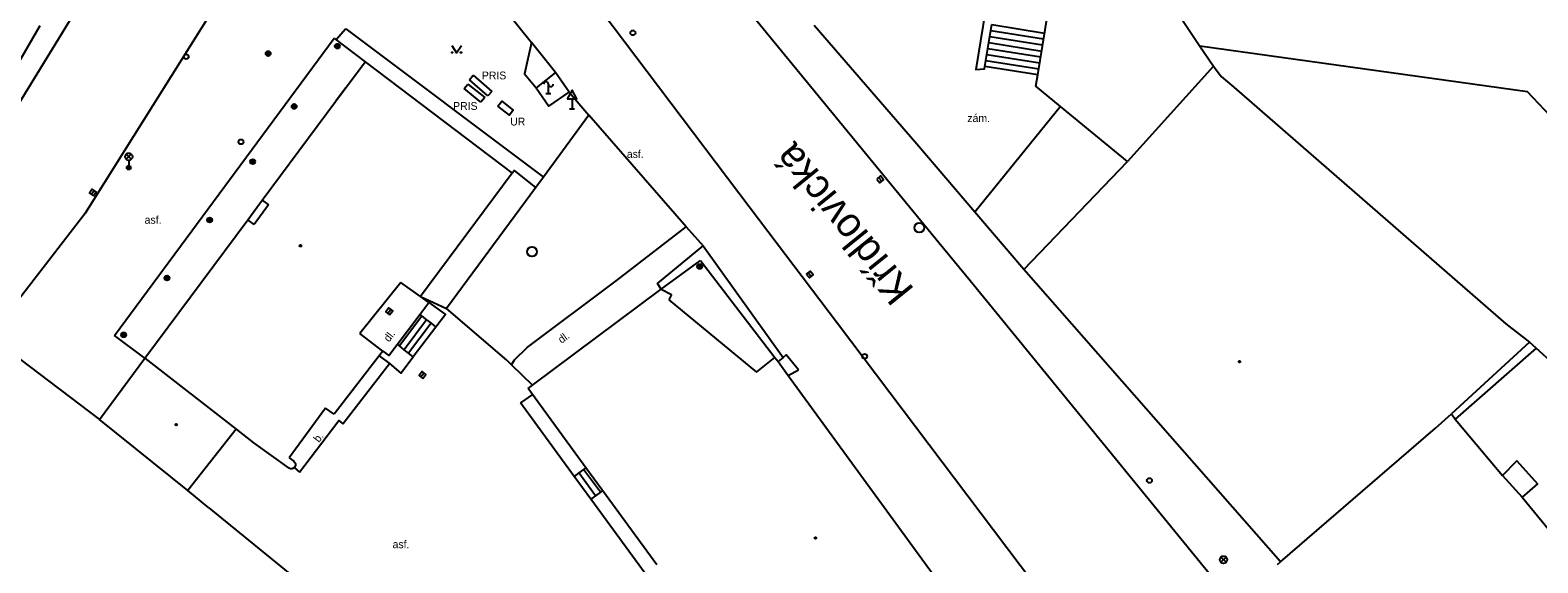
# Model space of a CAD drawing. Extents: x -599770 to -598493, y -1162076 to -1159209.
# Drawn here: x -599224.4 to -599147.3, y -1161384.7 to -1161357.5 of the extents above; entities that cross this region are included whole.
import ezdxf

# ---------------------------------------------------------------- set-up
doc = ezdxf.new("R2010")
doc.units = 0
doc.layers.add('Podklad', color=7, linetype='Continuous')

msp = doc.modelspace()

# ---------------------------------------------------------------- linework, layer by layer
at = {"layer": 'Podklad'}
for p, q in [((-599197.755, -1161360.78), (-599198.005, -1161360.78)), ((-599197.88, -1161360.78), (-599197.88, -1161360.28)), ((-599196.795, -1161361.54), (-599196.545, -1161361.54)), ((-599196.67, -1161361.031), (-599196.67, -1161361.54)), ((-599219.472, -1161364.12), (-599219.207, -1161363.855)), ((-599219.472, -1161363.855), (-599219.207, -1161364.12)), ((-599219.34, -1161364.175), (-599219.34, -1161364.55)), ((-599180.999, -1161365.053), (-599180.841, -1161365.247)), ((-599221.252, -1161365.922), (-599221.108, -1161365.718)), ((-599184.599, -1161369.913), (-599184.441, -1161370.107)), ((-599206.098, -1161371.987), (-599205.942, -1161371.793)), ((-599204.397, -1161375.239), (-599204.243, -1161375.041)), ((-599163.492, -1161384.71), (-599163.227, -1161384.445)), ((-599163.492, -1161384.445), (-599163.227, -1161384.71))]:
    msp.add_line(p, q, dxfattribs=at)
for points in [[(-599239.014, -1161385.727), (-599236.976, -1161381.672), (-599234.78, -1161377.7), (-599231.55, -1161372), (-599222.91, -1161357.95), (-599219.457, -1161352.277), (-599215.467, -1161346.967), (-599210.98, -1161342.07), (-599209.242, -1161340.985), (-599207.42, -1161340.046), (-599205.528, -1161339.259), (-599203.577, -1161338.631), (-599202.43, -1161338.36), (-599201.582, -1161338.165), (-599199.555, -1161337.864), (-599197.51, -1161337.73), (-599193.601, -1161337.831), (-599189.703, -1161338.151), (-599185.83, -1161338.69)], [(-599191.19, -1161352.2), (-599177.913, -1161368.369), (-599176.32, -1161370.31), (-599158.79, -1161391.75), (-599151.4, -1161400.84), (-599147.2, -1161405.85), (-599145.39, -1161407.58)], [(-599212.65, -1161353), (-599213.71, -1161354.36), (-599221.59, -1161366.91), (-599226.04, -1161372.65), (-599229.99, -1161377.9), (-599232.1, -1161380.86), (-599234.18, -1161384.1), (-599236.22, -1161387.65), (-599238.28, -1161391.75), (-599239.59, -1161395.19), (-599241.23, -1161400.43), (-599242.73, -1161406.61)], [(-599168.08, -1161353.08), (-599164.58, -1161358.34)], [(-599175.3, -1161355.02), (-599176.03, -1161359.53), (-599175.58, -1161359.5), (-599175.56, -1161359.38)], [(-599153.06, -1161412.26), (-599155.32, -1161409.26), (-599158.29, -1161405.32), (-599169.77, -1161390.15), (-599183.101, -1161372.518), (-599187.56, -1161366.62), (-599195.73, -1161355.8)], [(-599200.21, -1161356.34), (-599198.75, -1161358.15)], [(-599172.86, -1161359.81), (-599172.37, -1161356.78)], [(-599223.89, -1161357.31), (-599232.14, -1161371.53), (-599232.24, -1161371.71)], [(-599208.24, -1161357.45), (-599208.74, -1161358.02)], [(-599208.24, -1161357.45), (-599198.14, -1161365.03)], [(-599173.58, -1161369.76), (-599176.079, -1161366.827), (-599179.04, -1161363.35), (-599184.3, -1161357.28)], [(-599175.31, -1161357.85), (-599175.26, -1161357.54)], [(-599175.26, -1161357.54), (-599175.21, -1161357.24)], [(-599175.26, -1161357.54), (-599172.56, -1161357.97)], [(-599175.21, -1161357.24), (-599172.51, -1161357.67)], [(-599220.07, -1161373.12), (-599208.83, -1161357.93)], [(-599208.83, -1161357.93), (-599208.74, -1161358.02)], [(-599208.74, -1161358.02), (-599207.25, -1161359.14)], [(-599202.824, -1161358.315), (-599202.574, -1161358.69), (-599202.324, -1161358.315)], [(-599198.75, -1161358.15), (-599199.1, -1161359.76), (-599198.51, -1161360.47)], [(-599197.52, -1161359.68), (-599198.75, -1161358.15)], [(-599175.46, -1161358.77), (-599175.41, -1161358.46)], [(-599175.41, -1161358.46), (-599175.36, -1161358.15)], [(-599175.41, -1161358.46), (-599172.71, -1161358.89)], [(-599175.36, -1161358.15), (-599175.31, -1161357.85)], [(-599175.36, -1161358.15), (-599172.66, -1161358.59)], [(-599175.31, -1161357.85), (-599172.61, -1161358.28)], [(-599164.58, -1161358.34), (-599163.88, -1161359.36)], [(-599147.82, -1161360.68), (-599164.58, -1161358.34)], [(-599208.25, -1161360.49), (-599207.25, -1161359.14)], [(-599207.25, -1161359.14), (-599199.73, -1161364.83)], [(-599175.56, -1161359.38), (-599175.51, -1161359.07)], [(-599175.51, -1161359.07), (-599175.46, -1161358.77)], [(-599175.51, -1161359.07), (-599172.81, -1161359.5)], [(-599175.46, -1161358.77), (-599172.76, -1161359.2)], [(-599201.92, -1161360.06), (-599201.72, -1161359.83)], [(-599200.97, -1161360.88), (-599201.92, -1161360.06)], [(-599201.72, -1161359.83), (-599200.77, -1161360.65)], [(-599197.52, -1161359.68), (-599198.51, -1161360.47)], [(-599196.82, -1161360.69), (-599197.52, -1161359.68)], [(-599172.86, -1161359.81), (-599175.56, -1161359.38)], [(-599172.96, -1161360.39), (-599172.86, -1161359.81)], [(-599163.88, -1161359.36), (-599168.27, -1161364.24)], [(-599163.88, -1161359.36), (-599163.48, -1161359.9)], [(-599163.48, -1161359.9), (-599162.83, -1161360.43)], [(-599208.25, -1161360.49), (-599208.76, -1161361.17)], [(-599208.76, -1161361.17), (-599208.25, -1161360.49)], [(-599202.19, -1161360.51), (-599202, -1161360.28)], [(-599201.33, -1161361.2), (-599202.19, -1161360.51)], [(-599202, -1161360.28), (-599201.14, -1161360.97)], [(-599200.77, -1161360.65), (-599200.97, -1161360.88)], [(-599198.51, -1161360.47), (-599197.86, -1161361.41), (-599196.82, -1161360.69)], [(-599196.82, -1161360.69), (-599195.81, -1161361.87), (-599198.14, -1161365.03)], [(-599168.27, -1161364.24), (-599171.7, -1161361.424), (-599172.96, -1161360.39)], [(-599162.83, -1161360.43), (-599148.92, -1161372.53)], [(-599145.79, -1161362.82), (-599147.82, -1161360.68)], [(-599212.51, -1161366.21), (-599208.76, -1161361.17)], [(-599201.14, -1161360.97), (-599201.33, -1161361.2)], [(-599200.46, -1161361.4), (-599200.27, -1161361.16), (-599199.68, -1161361.62), (-599199.87, -1161361.86), (-599200.46, -1161361.4)], [(-599171.7, -1161361.424), (-599176.079, -1161366.827)], [(-599190.84, -1161367.57), (-599195.81, -1161361.87)], [(-599198.529, -1161365.556), (-599199.617, -1161364.691), (-599199.73, -1161364.83)], [(-599173.58, -1161369.76), (-599168.27, -1161364.24)], [(-599199.73, -1161364.83), (-599204.42, -1161371.13)], [(-599198.14, -1161365.03), (-599198.529, -1161365.556), (-599203.1, -1161371.74)], [(-599213.25, -1161367.22), (-599212.51, -1161366.21)], [(-599212.51, -1161366.21), (-599212.19, -1161366.45)], [(-599212.19, -1161366.45), (-599212.93, -1161367.45)], [(-599212.19, -1161366.45), (-599212.93, -1161367.45)], [(-599218.51, -1161374.28), (-599213.25, -1161367.22)], [(-599212.93, -1161367.45), (-599213.25, -1161367.22)], [(-599199.76, -1161374.62), (-599199.61, -1161374.36), (-599198.96, -1161373.73), (-599194.42, -1161370.33), (-599190.84, -1161367.57), (-599189.97, -1161368.55)], [(-599192.11, -1161370.76), (-599192.31, -1161370.47), (-599189.97, -1161368.55)], [(-599189.97, -1161368.55), (-599185.88, -1161374.24), (-599186.14, -1161374.45)], [(-599192.11, -1161370.76), (-599190.11, -1161369.29)], [(-599190.11, -1161369.29), (-599186.31, -1161374.24)], [(-599160.44, -1161384.68), (-599173.58, -1161369.76)], [(-599205.42, -1161370.42), (-599207.52, -1161373.02)], [(-599204.42, -1161371.13), (-599205.42, -1161370.42)], [(-599198.69, -1161375.66), (-599192.11, -1161370.76)], [(-599192.11, -1161370.76), (-599191.58, -1161371.03)], [(-599204.46, -1161372.05), (-599204, -1161371.43)], [(-599204, -1161371.43), (-599204.42, -1161371.13)], [(-599204.42, -1161371.13), (-599203.1, -1161371.74)], [(-599204, -1161371.43), (-599203.15, -1161372.05), (-599203.64, -1161372.69)], [(-599191.58, -1161371.03), (-599191.72, -1161371.3)], [(-599191.72, -1161371.3), (-599187.24, -1161374.99)], [(-599205.61, -1161373.58), (-599204.46, -1161372.05)], [(-599204.35, -1161372.14), (-599205.5, -1161373.66)], [(-599204.11, -1161372.32), (-599205.26, -1161373.85)], [(-599204.46, -1161372.05), (-599204.35, -1161372.14)], [(-599204.35, -1161372.14), (-599204.11, -1161372.32)], [(-599204.11, -1161372.32), (-599203.88, -1161372.5)], [(-599200, -1161374.39), (-599203.1, -1161371.74)], [(-599218.51, -1161374.28), (-599220.07, -1161373.12)], [(-599206.34, -1161373.92), (-599207.52, -1161373.02)], [(-599203.88, -1161372.5), (-599205.03, -1161374.03)], [(-599203.64, -1161372.69), (-599204.79, -1161374.21)], [(-599203.88, -1161372.5), (-599203.64, -1161372.69)], [(-599148.92, -1161372.53), (-599147.71, -1161373.46)], [(-599206.34, -1161373.92), (-599206.53, -1161374.16)], [(-599206.34, -1161373.92), (-599206.04, -1161374.15), (-599205.61, -1161373.58)], [(-599205.5, -1161373.66), (-599205.61, -1161373.58)], [(-599205.26, -1161373.85), (-599205.5, -1161373.66)], [(-599205.03, -1161374.03), (-599205.26, -1161373.85)], [(-599147.71, -1161373.46), (-599151.7, -1161377.13)], [(-599147.38, -1161373.77), (-599151.51, -1161377.39)], [(-599147.38, -1161373.77), (-599147.71, -1161373.46)], [(-599145.57, -1161375.41), (-599147.38, -1161373.77)], [(-599224.93, -1161374.32), (-599220.84, -1161377.42)], [(-599220.84, -1161377.42), (-599218.51, -1161374.28)], [(-599218.51, -1161374.28), (-599213.85, -1161377.91), (-599212.96, -1161378.6)], [(-599206.53, -1161374.16), (-599208.83, -1161377.15)], [(-599208.4, -1161377.63), (-599206.01, -1161374.56)], [(-599206.53, -1161374.16), (-599206.01, -1161374.56)], [(-599206.01, -1161374.56), (-599205.43, -1161375.04), (-599204.79, -1161374.21)], [(-599204.79, -1161374.21), (-599205.03, -1161374.03)], [(-599200, -1161374.39), (-599199.76, -1161374.62)], [(-599199.76, -1161374.62), (-599198.69, -1161375.66)], [(-599187.24, -1161374.99), (-599186.31, -1161374.24)], [(-599186.31, -1161374.24), (-599186.14, -1161374.45)], [(-599186.14, -1161374.45), (-599185.62, -1161375.163), (-599173.15, -1161392.26)], [(-599185.087, -1161374.879), (-599185.72, -1161374.11), (-599185.88, -1161374.24)], [(-599185.62, -1161375.163), (-599185.087, -1161374.879)], [(-599198.7, -1161376.13), (-599199.3, -1161376.57)], [(-599198.92, -1161375.83), (-599198.69, -1161375.66)], [(-599198.7, -1161376.13), (-599198.92, -1161375.83)], [(-599195.96, -1161379.88), (-599198.7, -1161376.13)], [(-599209.28, -1161376.83), (-599211.13, -1161379.37)], [(-599208.83, -1161377.15), (-599209.28, -1161376.83)], [(-599196.56, -1161380.32), (-599199.3, -1161376.57)], [(-599215.24, -1161381.92), (-599216.32, -1161381.05), (-599220.84, -1161377.42)], [(-599210.6, -1161380.1), (-599208.6, -1161377.46), (-599208.4, -1161377.63)], [(-599152.52, -1161377.85), (-599151.7, -1161377.13)], [(-599151.7, -1161377.13), (-599151.51, -1161377.39)], [(-599151.51, -1161377.39), (-599149.09, -1161380.27)], [(-599213.85, -1161377.91), (-599216.32, -1161381.05)], [(-599160.44, -1161384.68), (-599152.52, -1161377.85)], [(-599212.96, -1161378.6), (-599211.15, -1161379.91)], [(-599211.06, -1161379.94), (-599211.15, -1161379.91)], [(-599211.13, -1161379.37), (-599210.9, -1161379.54)], [(-599210.98, -1161379.93), (-599211.06, -1161379.94)], [(-599210.9, -1161379.89), (-599210.98, -1161379.93)], [(-599210.9, -1161379.54), (-599210.82, -1161379.66)], [(-599210.88, -1161379.87), (-599210.9, -1161379.89)], [(-599210.85, -1161379.83), (-599210.88, -1161379.87)], [(-599210.88, -1161379.87), (-599210.6, -1161380.1)], [(-599210.82, -1161379.75), (-599210.85, -1161379.83)], [(-599210.82, -1161379.66), (-599210.82, -1161379.75)], [(-599196.08, -1161379.97), (-599196.32, -1161380.14)], [(-599195.96, -1161379.88), (-599196.08, -1161379.97)], [(-599195.22, -1161381.13), (-599196.08, -1161379.97)], [(-599195.11, -1161381.05), (-599195.96, -1161379.88)], [(-599149.09, -1161380.27), (-599148.36, -1161379.53), (-599147.3, -1161380.7), (-599148.1, -1161381.38)], [(-599196.32, -1161380.14), (-599196.56, -1161380.32)], [(-599195.71, -1161381.49), (-599196.56, -1161380.32)], [(-599195.47, -1161381.31), (-599196.32, -1161380.14)], [(-599149.09, -1161380.27), (-599148.1, -1161381.38)], [(-599195.47, -1161381.31), (-599195.71, -1161381.49)], [(-599192.94, -1161385.28), (-599195.71, -1161381.49)], [(-599195.22, -1161381.13), (-599195.47, -1161381.31)], [(-599195.11, -1161381.05), (-599195.22, -1161381.13)], [(-599192.34, -1161384.84), (-599195.11, -1161381.05)], [(-599148.1, -1161381.38), (-599146.68, -1161383.11)], [(-599215.24, -1161381.92), (-599209.53, -1161386.58)], [(-599160.6, -1161384.82), (-599160.44, -1161384.68)]]:
    msp.add_lwpolyline(points, dxfattribs=at)
for points in [[(-599196.92, -1161361.031), (-599196.42, -1161361.031), (-599196.67, -1161360.598)], [(-599181.096, -1161365.133), (-599180.937, -1161365.326), (-599180.744, -1161365.167), (-599180.903, -1161364.974)], [(-599221.149, -1161365.994), (-599221.006, -1161365.789), (-599221.211, -1161365.646), (-599221.354, -1161365.851)], [(-599184.696, -1161369.993), (-599184.537, -1161370.186), (-599184.344, -1161370.027), (-599184.503, -1161369.834)], [(-599206.001, -1161372.066), (-599205.844, -1161371.871), (-599206.039, -1161371.714), (-599206.196, -1161371.909)], [(-599204.298, -1161375.315), (-599204.145, -1161375.118), (-599204.342, -1161374.965), (-599204.495, -1161375.162)]]:
    msp.add_lwpolyline(points, close=True, dxfattribs=at)
for centre, radius in [((-599193.56, -1161357.66), 0.125), ((-599208.67, -1161358.34), 0.125), ((-599208.67, -1161358.34), 0.1), ((-599208.67, -1161358.34), 0.075), ((-599208.67, -1161358.34), 0.05), ((-599208.67, -1161358.34), 0.025), ((-599216.4, -1161358.88), 0.125), ((-599212.21, -1161358.72), 0.125), ((-599212.21, -1161358.72), 0.1), ((-599212.21, -1161358.72), 0.075), ((-599212.21, -1161358.72), 0.05), ((-599212.21, -1161358.72), 0.025), ((-599202.8, -1161358.665), 0.025), ((-599202.35, -1161358.665), 0.025), ((-599210.88, -1161361.42), 0.125), ((-599210.88, -1161361.42), 0.1), ((-599210.88, -1161361.42), 0.075), ((-599210.88, -1161361.42), 0.05), ((-599210.88, -1161361.42), 0.025), ((-599213.6, -1161363.23), 0.125), ((-599219.34, -1161363.988), 0.188), ((-599219.34, -1161364.55), 0.1), ((-599219.34, -1161364.55), 0.0723), ((-599219.34, -1161364.55), 0.0438), ((-599213, -1161364.24), 0.125), ((-599213, -1161364.24), 0.1), ((-599213, -1161364.24), 0.075), ((-599213, -1161364.24), 0.05), ((-599213, -1161364.24), 0.025), ((-599215.2, -1161367.22), 0.125), ((-599215.2, -1161367.22), 0.1), ((-599215.2, -1161367.22), 0.075), ((-599215.2, -1161367.22), 0.05), ((-599215.2, -1161367.22), 0.025), ((-599178.92, -1161367.61), 0.25), ((-599210.56, -1161368.54), 0.045), ((-599210.56, -1161368.54), 0.0199), ((-599198.72, -1161368.84), 0.25), ((-599217.38, -1161370.19), 0.125), ((-599217.38, -1161370.19), 0.1), ((-599190.15, -1161369.6), 0.125), ((-599190.15, -1161369.6), 0.1), ((-599190.15, -1161369.6), 0.075), ((-599190.15, -1161369.6), 0.05), ((-599190.15, -1161369.6), 0.025), ((-599217.38, -1161370.19), 0.075), ((-599217.38, -1161370.19), 0.05), ((-599217.38, -1161370.19), 0.025), ((-599219.6, -1161373.09), 0.125), ((-599219.6, -1161373.09), 0.1), ((-599219.6, -1161373.09), 0.075), ((-599219.6, -1161373.09), 0.05), ((-599219.6, -1161373.09), 0.025), ((-599181.71, -1161374.19), 0.125), ((-599162.54, -1161374.46), 0.045), ((-599162.54, -1161374.46), 0.0199), ((-599216.91, -1161377.68), 0.045), ((-599216.91, -1161377.68), 0.0199), ((-599167.15, -1161380.53), 0.125), ((-599184.23, -1161383.47), 0.045), ((-599184.23, -1161383.47), 0.0199), ((-599163.36, -1161384.578), 0.188)]:
    msp.add_circle(centre, radius, dxfattribs=at)
for centre, start, end in [((-599198.005, -1161360.28), 0, 180), ((-599197.755, -1161360.28), 180, 0)]:
    msp.add_arc(centre, 0.125, start, end, dxfattribs=at)

# ---------------------------------------------------------------- texts
for s, p in [('PRIS', (-599201.283, -1161360.039)), ('PRIS', (-599202.754, -1161361.598)), ('UR', (-599199.836, -1161362.394)), ('zám.', (-599176.46, -1161362.22)), ('asf.', (-599193.87, -1161364.05)), ('asf.', (-599218.527, -1161367.414)), ('asf.', (-599205.85, -1161383.99))]:
    msp.add_text(s, height=0.4, dxfattribs=at).set_placement(p)
for s, height, rotation, p in [('Křídlovická', 1.5, 128.96968, (-599179.133, -1161370.775)), ('dl.', 0.4, 52.6, (-599206.03, -1161373.49)), ('dl.', 0.4, 36.01, (-599197.21, -1161373.55)), ('b.', 0.4, 51.82, (-599209.62, -1161378.62))]:
    msp.add_text(s, height=height, rotation=rotation, dxfattribs=at).set_placement(p)

doc.saveas('drawing.dxf')
